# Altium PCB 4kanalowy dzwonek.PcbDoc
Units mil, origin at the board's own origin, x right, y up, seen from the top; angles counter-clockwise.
Board outline 6000 x 4000 mil, 2 copper layers (Top Layer, Bottom Layer); 51 components, 32 nets, 144 pads, 1 vias.
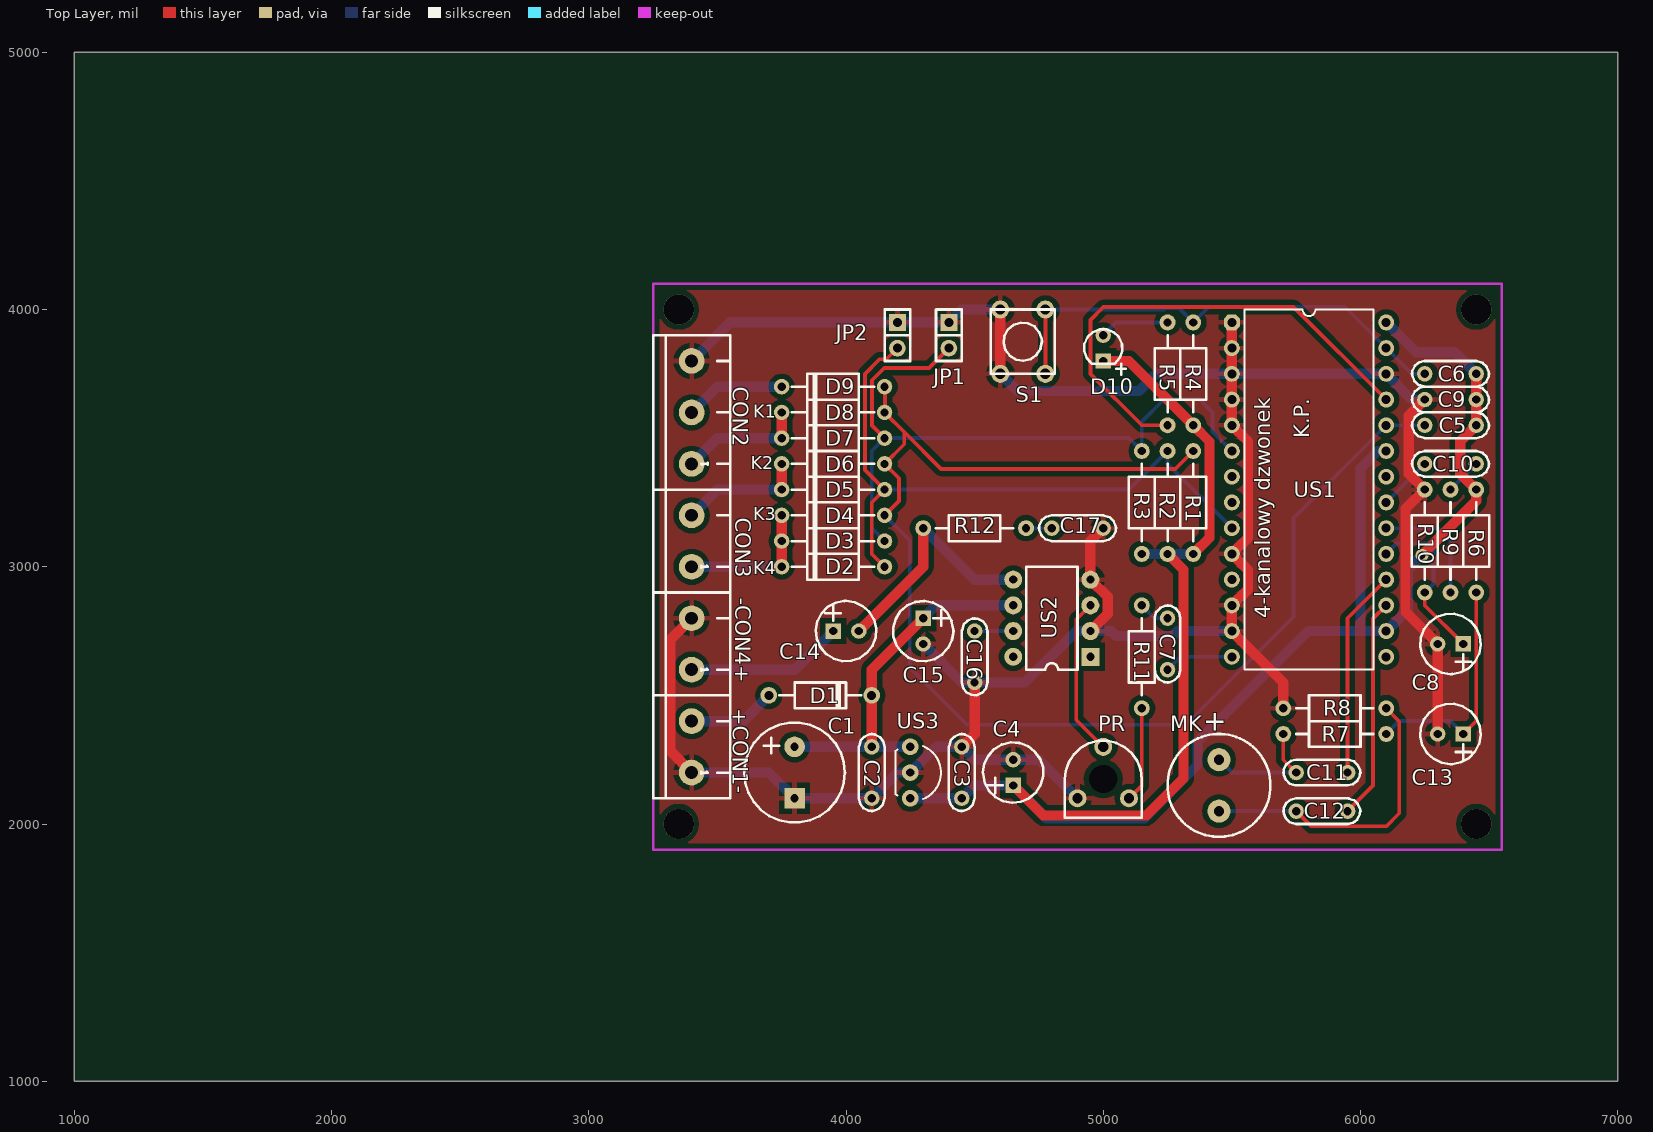
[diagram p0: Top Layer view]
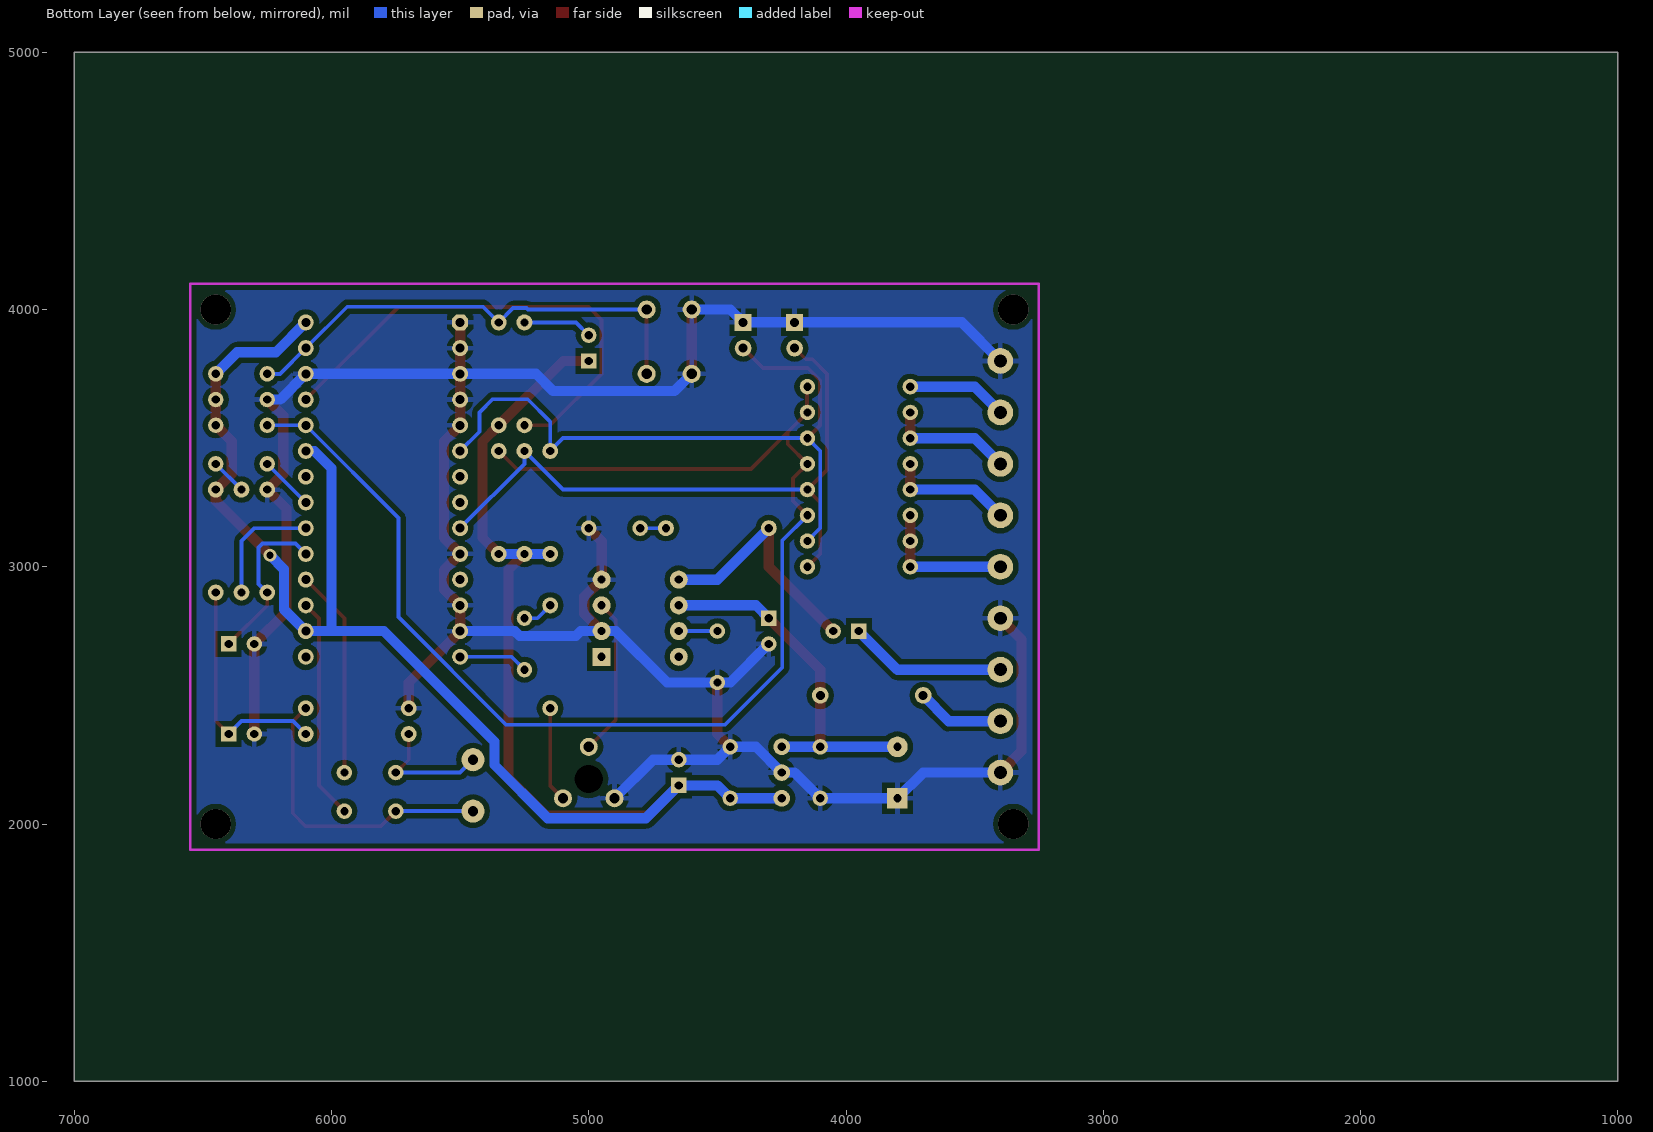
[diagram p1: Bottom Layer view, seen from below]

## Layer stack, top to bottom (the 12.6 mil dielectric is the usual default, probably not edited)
Top Layer: signal copper 1.4
Dielectric: dielectric 12.6, FR-4, Dk 4.8
Bottom Layer: signal copper 1.4

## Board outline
1000,1000 7000,1000 7000,5000 1000,5000

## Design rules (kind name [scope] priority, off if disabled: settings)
Clearance [All] p1: gap=20
ComponentClearance [All] p1: gap=10 collisioncheckmode=0
PolygonConnect [All] p1: connectstyle=Relief reliefconductorwidth=20 reliefentries=4 polygonreliefangle="90 Angle"
RoutingVias [All] p1: holewidth=28 width=50 viastyle="Through Hole" minholewidth=28 minwidth=50 maxholewidth=28 maxwidth=50
SolderMaskExpansion [All] p1: expansion=4
TestPointUsage [All] p1: valid=0 allowmultiple=FALSE
Testpoint [All] p1: side=15 testpointundercomponent=TRUE minsize=40 maxsize=100 preferedsize=60 minholesize=0 maxholesize=40 preferedholesize=32 testpointgrid=1 style=1023 order=-539222988
Width Width_1 [InNet('VIN') Or InNet('VCC') Or  InNet('GND') Or InNet('NetC14_2') Or InNet('NetC14_1') Or InNet('NetCON1_2') Or InNet('GND') Or InNet('GND')] p1: maxlimit=40 minlimit=10 preferedwidth=40
Width [All] p2: maxlimit=15 minlimit=10 preferedwidth=15
17 further rules are at their usual default settings.

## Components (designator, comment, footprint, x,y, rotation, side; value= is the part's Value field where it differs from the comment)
+CON1- "" con2-5 3400,2300 r270 top (schematic designator CON1)
-CON4+ "" con2-5 3400,2700 r270 top (schematic designator CON4)
C1 "470u" elektr2 3800,2200 r180 top
C2 "100n" cap1 4100,2200 r270 top
C3 "100n" cap1 4450,2200 r90 top
C4 "100u" elektr1 4650,2150 r180 top
C5 "100nF" cap1 6350,3550 r180 top
C6 "Cap" cap1 6350,3750 r0 top
C7 "220n" cap1 5250,2700 r270 top
C8 "4,7u" elektr1 6400,2700 r270 top
C9 "100n" cap1 6350,3650 r180 top
C10 "100n" cap1 6350,3400 r0 top
C11 "100n" cap1 5850,2200 r180 top
C12 "100n" cap1 5850,2050 r180 top
C13 "220u" elektr1 6400,2350 r270 top
C14 "220uF" elektr1 3950,2750 r90 top
C15 "100uF" elektr1 4300,2800 r0 top
C16 "100nF" CAP1 4500,2650 r270 top
C17 "100nF" CAP1 4900,3150 r0 top
CON2 "Header 3" CON3-5 3400,3600 r90 top
CON3 "Header 2" CON2-5 3400,3100 r270 top
D1 "1N4007" dioda#1 3900,2500 r0 top
D2 "1N4148" dioda#2 3950,3000 r180 top
D3 "1N4148" dioda#2 3950,3100 r180 top
D4 "1N4148" dioda#2 3950,3200 r180 top
D5 "1N4148" dioda#2 3950,3300 r180 top
D6 "1N4148" dioda#2 3950,3400 r180 top
D7 "1N4148" dioda#2 3950,3500 r180 top
D8 "1N4148" dioda#2 3950,3600 r180 top
D9 "1N4148" dioda#2 3950,3700 r180 top
D10 "LED0" LED3 5000,3800 r0 top
JP1 "JUMPER" SIP2 4400,3950 r270 top
JP2 "JUMPER" SIP2 4200,3950 r270 top
MK "" CP_S 5450,2250 r180 top
PR "10k" POT 5000,2200 r0 top
R1 "Res2" r 5350,3250 r270 top
R2 "Res2" r 5250,3250 r270 top
R3 "Res2" r 5150,3250 r270 top
R4 "Res2" r 5350,3750 r270 top
R5 "Res2" r 5250,3750 r90 top
R6 "1k" r 6450,3100 r90 top
R7 "10k" r 5900,2350 r0 top
R8 "10k" r 5900,2450 r0 top
R9 "5,1k" r 6350,3100 r90 top
R10 "470k" r 6250,3100 r270 top
R11 "Res2" r 5150,2650 r90 top
R12 "30" R 4500,3150 r0 top
S1 "SW-PB" key1 4600,3750 r0 top
US1 "ISD 1420" dip-28 5500,3950 r0 top
US2 "LM386" DIP8 4950,2650 r180 top
US3 "78l05" to-92C 4250,2300 r0 top

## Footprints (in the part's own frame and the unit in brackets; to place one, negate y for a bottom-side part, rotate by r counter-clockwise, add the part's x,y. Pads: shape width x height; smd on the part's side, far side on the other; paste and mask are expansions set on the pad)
cap1 [mil]
  round 60 hole 32: 1(-100,0) 2(100,0)
  silkscreen extent -150,-50 150,50
CAP1 [mil]
  round 60 hole 32: 1(-100,0) 2(100,0)
  silkscreen extent -150,-50 150,50
con2-5 [mil]
  round 100 hole 50: 1(100,0) 2(-100,0)
  silkscreen extent -200,-150 200,150
CON2-5 [mil]
  round 100 hole 50: 1(100,0) 2(-100,0)
  silkscreen extent -200,-150 200,150
CON3-5 [mil]
  round 100 hole 50: 1(-200,0) 2(0,0) 3(200,0)
  silkscreen extent -300,-150 300,150
CP_S [mil]
  round 90 hole 40: 1(0,0) 2(0,200)
  silkscreen extent -200,-100 200,300
dioda#1 [mil]
  round 65 hole 35: 1(-200,0) 2(200,0)
  silkscreen extent -160,-50 160,50
dioda#2 [mil]
  round 60 hole 32: 1(-200,0) 2(200,0)
  silkscreen extent -160,-50 160,50
DIP8 [mil]
  rect 70x70 hole 32: 1(0,0)
  round 70 hole 32: 2(0,-100) 3(0,-200) 4(0,-300) 5(300,-300) 6(300,-200) 7(300,-100) 8(300,0)
  silkscreen extent 50,-350 250,50
dip-28 [mil]
  oct 62x62 hole 35: 1(0,0)
  round 62 hole 35: 2(0,-100) 3(0,-200) 4(0,-300) 5(0,-400) 6(0,-500) 7(0,-600) 8(0,-700) 9(0,-800) 10(0,-900) 11(0,-1000) 12(0,-1100) 13(0,-1200) 14(0,-1300) 15(600,-1300) 16(600,-1200) 17(600,-1100) 18(600,-1000) 19(600,-900) 20(600,-800) 21(600,-700) 22(600,-600) 23(600,-500) 24(600,-400) 25(600,-300) 26(600,-200) 27(600,-100) 28(600,0)
  silkscreen extent 50,-1350 550,50
elektr1 [mil]
  rect 60x60 hole 32: 1(0,0)
  round 60 hole 32: 2(0,-100)
  silkscreen extent -117,-167 118,67
elektr2 [mil]
  round 80 hole 32: 1(0,-100)
  rect 80x80 hole 32: 2(0,100)
  silkscreen extent -196,-194 196,194
key1 [mil]
  round 70 hole 40: 1(0,0) 1(0,250) 2(175,0) 2(175,250)
  silkscreen extent -38,0 212,250
LED3 [mil]
  rect 60x60 hole 32: 1(0,0)
  round 60 hole 32: 2(0,100)
  silkscreen extent -74,-53 87,123
POT [mil]
  round 60 hole 110: 0(0,-25)
  round 70 hole 40: 1(-100,-100) 2(100,-100) 3(0,100)
  silkscreen extent -150,-175 150,124
r [mil]
  round 62 hole 32: 1(-200,0) 2(200,0)
  silkscreen extent -150,-50 150,50
R [mil]
  round 62 hole 32: 1(-200,0) 2(200,0)
  silkscreen extent -150,-50 150,50
SIP2 [mil]
  rect 65x65 hole 35: 1(0,0)
  round 65 hole 35: 2(100,0)
  silkscreen extent -50,-50 150,50
to-92C [mil]
  round 65 hole 32: 1(0,0) 2(0,-100) 3(0,-200)
  silkscreen extent -58,-203 119,3

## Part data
+CON1- -CON4+: library part CON2
C1 C4 C8 C13: library part ELECTRO2, "Electrolytic Capacitor"
C2 C3: library part CAP
C5: library part Cap, "Capacitor"
C6: "Capacitor"
C7 C9 C10 C11 C12 C16 C17: library part CAP, "Capacitor"
C14 C15: library part CP, "Capacitor"
CON2: "Header, 3-Pin"
CON3: "Header, 2-Pin"
D1: library part DIODE, "Diode"
D2 D3 D4 D5 D6 D7 D8 D9: library part Diode, "Default Diode"
D10: "Typical INFRARED GaAs LED"
MK: library part MICROPHONE2, "Microphone"
PR: library part POT2, "Potentiometer"
R1 R2 R3 R4 R5 R11: "Resistor"
R6 R7 R8 R9 R10 R12: library part RES2
S1: "Switch"
US3: library part VOLTREG

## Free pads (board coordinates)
  round 118.11 hole 118.11: 0(3350,2000) 1(3350,4000) 2(6450,4000) 3(6450,2000)

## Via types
v1: diameter 50, hole 28, Top Layer to Bottom Layer, 1 vias

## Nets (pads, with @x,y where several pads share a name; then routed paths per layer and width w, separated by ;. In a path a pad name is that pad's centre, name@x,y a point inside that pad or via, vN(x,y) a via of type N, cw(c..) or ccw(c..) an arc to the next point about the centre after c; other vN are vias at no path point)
+VCC: 
GND: +CON1-.1 -CON4+.2 C1.2 C2.2 C3.2 C4.2 C8.2 C9.2 C13.2 C15.2 C16.2 C17.2 CON2.3 JP1.1 JP2.1 PR.1 R8.1 R10.1 S1.1 US1.1 US1.2 US1.3 US1.4 US1.5 US1.10 US1.12 US1.13 US1.26 US2.2 US2.4 US3.2 | length 10883.8
  Top Layer w40: +CON1-.1 3318,2282 3318,2718 -CON4+.2 ; C3.2 4500,2350 C16.2 ; S1.1@4600,3750 S1.1@4600,4000 ; US2.2 5017,2817 5017,2883 US2.4 4950,3100 C17.2 ; US1.1 US1.2 US1.3 US1.4 US1.5 5563,3487 5563,3113 US1.10 5563,2987 5563,2913 US1.12 US1.13 5700,2550 R8.1 ; C9.2 6188,3588 6188,3362 R10.1 6175.08,3225.08 6175.08,2824.92 C8.2 C13.2
  Bottom Layer w40: +CON1-.1 3700,2200 C1.2 C2.2 4200,2200 US3.2 4350,2300 C3.2 4500,2250 C4.2 4750,2250 PR.1 ; CON2.3 3550,3950 JP2.1 JP1.1 4450,4000 S1.1@4600,4000 ; C15.2 4450,2550 C16.2 4695,2550 4895,2750 US2.2 5032,2750 5051,2731 5268,2731 5287,2750 US1.13 ; S1.1@4600,3750 4667,3683 5138,3683 5205,3750 US1.3 US1.26 6200,3650 C9.2
NetC5_2: C5.2 D4.1 D6.1 D8.1 D9.1 R1.1 US1.24 | length 5258.2
  Top Layer w15: D4.1 4206,3256 4206,3344 D6.1 4226.5,3476.5 4226.5,3523.5 ; D9.1 4152,3698 4152,3602 D8.1 4226.5,3523.5 ; R1.1 5280,3380 4370,3380 4226.5,3523.5
  Bottom Layer w15: D4.1 4248,3102 4248,2608 4470,2386 5322,2386 5740,2804 5740,3190 US1.24 C5.2
NetC6_1: C6.1 R4.1 S1.2 US1.27 | length 1884.1
  Top Layer w15: S1.2@4775,3750 S1.2@4775,4000
  Bottom Layer w15: S1.2@4775,4000 5236,4000 5242,4006 5294,4006 R4.1 5411,4011 5939,4011 US1.27 6200,3750 C6.1
NetC7_1: C7.1 R11.2 | length 120.7
  Bottom Layer w15: R11.2 5200,2800 C7.1
NetC7_2: C7.2 US1.14 | length 270.7
  Bottom Layer w15: C7.2 5300,2650 US1.14
NetC8_1: C8.1 R10.2 US1.19 | length 657.4
  Top Layer w15: R10.2 6250,2850 C8.1
  Bottom Layer w15: US1.19 6140.1,3090.1 6268.4,3090.1 6283.5,3075 6283.5,2933.5 R10.2
NetC10_1: C10.1 US1.21 | length 212.1
  Bottom Layer w15: US1.21 C10.1
NetC10_2: C10.2 R9.2 | length 141.4
  Bottom Layer w15: R9.2 C10.2
NetC11_1: C11.1 US1.18 | length 812.1
  Top Layer w15: C11.1 5950,2800 US1.18
NetC11_2: C11.2 MK.1 R7.1 | length 491.4
  Top Layer w15: R7.1 5700,2250 C11.2
  Bottom Layer w15: MK.1 5500,2200 C11.2
NetC12_1: C12.1 US1.17 | length 862.1
  Top Layer w15: C12.1 6049,2149 6049,2799 US1.17
NetC12_2: C12.2 MK.2 R8.2 | length 1175.7
  Top Layer w15: C12.2 5809,1991 6100,1991 6151,2042 6151,2399 R8.2
  Bottom Layer w15: MK.2 C12.2
NetC13_1: C13.1 R6.1 R7.2 | length 912.1
  Top Layer w15: C13.1 6450,2400 R6.1
  Bottom Layer w15: R7.2 6150,2400 6350,2400 C13.1
NetC14_1: -CON4+.1 C14.1 | length 612.1
  Bottom Layer w40: -CON4+.1 3800,2600 C14.1
NetC14_2: C14.2 R12.1 US2.5 | length 936.4
  Top Layer w40: C14.2 4300,3000 R12.1
  Bottom Layer w40: R12.1 4500,2950 US2.5
NetC16_1: C16.1 US2.7 | length 150
  Bottom Layer w15: C16.1 US2.7
NetC17_1: C17.1 R12.2 | length 100
  Bottom Layer w15: R12.2 C17.1
NetCON1_2: +CON1-.2 D1.1 | length 341.4
  Bottom Layer w40: +CON1-.2 3600,2400 D1.1
NetCON2_1: CON2.1 D7.2 D8.2 | length 491.4
  Top Layer w40: D7.2 D8.2
  Bottom Layer w40: CON2.1 3500,3500 D7.2
NetCON2_2: CON2.2 D9.2 | length 391.4
  Bottom Layer w40: CON2.2 3500,3700 D9.2
NetCON3_1: CON3.1 D2.2 D3.2 D4.2 | length 550
  Top Layer w40: D2.2 D3.2 D4.2
  Bottom Layer w40: CON3.1 D2.2
NetCON3_2: CON3.2 D5.2 D6.2 | length 491.4
  Top Layer w40: D5.2 D6.2
  Bottom Layer w40: CON3.2 3500,3300 D5.2
NetD2_1: D2.1 D5.1 JP2.2 R2.1 US1.9 | length 2556.7
  Top Layer w15: D2.1 4100,3050 4100,3250 D5.1 4073.5,3376.5 4073.5,3750 4130.18,3806.68 4156.68,3806.68 JP2.2
  Bottom Layer w15: D5.1 5100,3300 R2.1 5250,3400 US1.9
NetD3_1: D3.1 D7.1 JP1.2 R3.1 US1.6 | length 2686.1
  Top Layer w15: D7.1 4100.5,3549.5 4100.5,3725 4148.5,3773 4323,3773 JP1.2
  Bottom Layer w15: D3.1 4100,3150 4100,3450 D7.1 5100,3500 R3.1 5150,3564 5237,3651 5374,3651 5425,3600 5425,3525 US1.6
NetD10_2: D10.2 R5.2 | length 270.7
  Bottom Layer w15: D10.2 5050,3950 R5.2
NetPR_1: PR.2 R11.1 | length 370.7
  Top Layer w15: PR.2 5150,2150 R11.1
NetPR_2: PR.3 US2.3 | length 616.3
  Top Layer w15: US2.3 4895,2795 4895,2405 PR.3
NetR5_1: R5.1 US1.25 | length 1912.7
  Top Layer w15: R5.1 5150,3550 4950,3750 4950,3960 5000,4010 5740,4010 US1.25
NetR9_1: R9.1 US1.20 | length 470.7
  Bottom Layer w15: US1.20 6300,3150 6350,3100 R9.1
VCC: C3.1 C4.1 C5.1 C6.2 C9.1 D10.1 R1.2 R2.2 R3.2 R4.2 R6.2 US1.16 US1.23 US1.28 US3.3 | length 7542.4
  Top Layer w40: C4.1 4767,2033 5167,2033 5312,2178 5312,2988 R2.2 ; D10.1 5100,3800 R4.2 5413,3487 5413,3113 R1.2 ; v1(6239,3045) 6450,3256 R6.2 6388,3362 6388,3488 C5.1 C9.1 C6.2
  Bottom Layer w40: US3.3 C3.1 4500,2150 C4.1 4778,2022 5159,2022 5366.35,2229.35 5366.35,2320.35 5796,2750 US1.16 6185,2835 6185,2991 v1(6239,3045) ; R3.2 R2.2 R1.2 ; 6000,2750 6000,3382.82 6067.18,3450 US1.23 ; US1.28 6216,3834 6366,3834 C6.2
VIN: C1.1 C2.1 C15.1 D1.2 US2.6 US3.1 | length 1403.6
  Top Layer w40: C2.1 D1.2 4100,2600 C15.1
  Bottom Layer w40: C1.1 C2.1 US3.1 ; C15.1 4350,2850 US2.6
pads on no net: PR.0 US1.7 US1.8 US1.11 US1.15 US1.22 US2.1 US2.8

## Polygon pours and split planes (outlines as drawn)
GND on Top Layer (solid, remove dead copper): 3250,4100 6550,4100 6550,1900 3250,1900
GND on Bottom Layer (solid, remove dead copper): 3250,4100 6550,4100 6550,1900 3250,1900

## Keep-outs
Keep-Out Layer:
  lines w10: 3250,1900 3250,4100 6550,4100 6550,1900 3250,1900

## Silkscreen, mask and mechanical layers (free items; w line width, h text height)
Top Overlay:
  text "K1" at 3640,3580 h50
  text "K.P." at 5800,3500 h60 r90
  text "K2" at 3630,3380 h50
  text "K3" at 3640,3180 h50
  text "K4" at 3640,2970 h50
  text "4-kanalowy dzwonek" at 5650,2800 h60 r90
